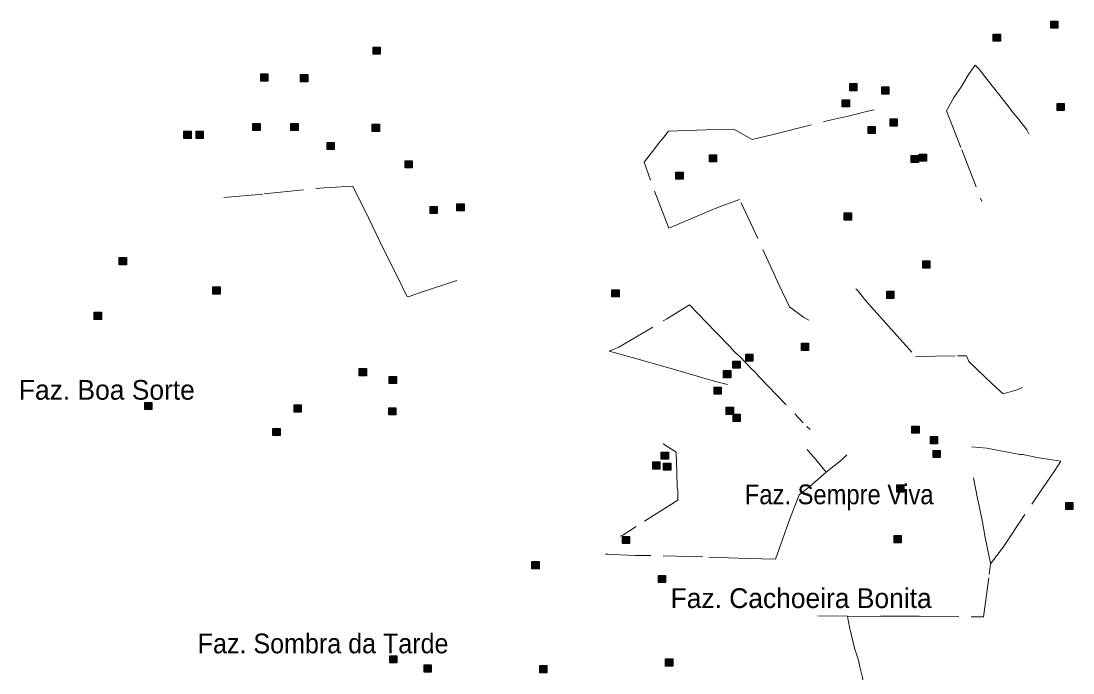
# Model space of a CAD drawing. Extents: x 393.5 to 446.9, y 8064.8 to 8120.4.
# Drawn here: x 417.84 to 426.38, y 8104.16 to 8109.45 of the extents above; entities that cross this region are included whole.
import ezdxf

# ---------------------------------------------------------------- set-up
doc = ezdxf.new("R2010")
doc.units = 0
doc.header["$LTSCALE"] = 0.064
doc.linetypes.add('DOT_DASHED', pattern=[7.7, 5, -1.2, 0.3, -1.2])
doc.layers.add('2', color=7, linetype='Continuous', lineweight=25)
doc.layers.add('22', color=7, linetype='DOT_DASHED', lineweight=13)
doc.layers.add('61', color=7, linetype='Continuous')

msp = doc.modelspace()

# ---------------------------------------------------------------- hatches: boundary and pattern name
at = {"layer": '2'}
for points in [[(426.1945, 8109.4478), (426.2525, 8109.4478), (426.2525, 8109.3898), (426.1945, 8109.3898)], [(425.7282, 8109.3416), (425.7862, 8109.3416), (425.7862, 8109.2836), (425.7282, 8109.2836)], [(420.6996, 8109.2372), (420.7576, 8109.2372), (420.7576, 8109.1792), (420.6996, 8109.1792)], [(419.7879, 8109.0185), (419.8459, 8109.0185), (419.8459, 8108.9605), (419.7879, 8108.9605)], [(420.1104, 8109.013), (420.1684, 8109.013), (420.1684, 8108.955), (420.1104, 8108.955)], [(424.565, 8108.941), (424.623, 8108.941), (424.623, 8108.883), (424.565, 8108.883)], [(424.8245, 8108.9129), (424.8825, 8108.9129), (424.8825, 8108.8549), (424.8245, 8108.8549)], [(424.5039, 8108.8094), (424.5619, 8108.8094), (424.5619, 8108.7514), (424.5039, 8108.7514)], [(426.247, 8108.7795), (426.305, 8108.7795), (426.305, 8108.7215), (426.247, 8108.7215)], [(419.7247, 8108.6181), (419.7827, 8108.6181), (419.7827, 8108.5601), (419.7247, 8108.5601)], [(420.0328, 8108.6181), (420.0908, 8108.6181), (420.0908, 8108.5601), (420.0328, 8108.5601)], [(420.6916, 8108.6109), (420.7496, 8108.6109), (420.7496, 8108.5529), (420.6916, 8108.5529)], [(424.8917, 8108.6537), (424.9497, 8108.6537), (424.9497, 8108.5957), (424.8917, 8108.5957)], [(419.165, 8108.5539), (419.223, 8108.5539), (419.223, 8108.4959), (419.165, 8108.4959)], [(419.2628, 8108.5542), (419.3208, 8108.5542), (419.3208, 8108.4962), (419.2628, 8108.4962)], [(424.7134, 8108.5925), (424.7714, 8108.5925), (424.7714, 8108.5345), (424.7134, 8108.5345)], [(420.3263, 8108.4635), (420.3843, 8108.4635), (420.3843, 8108.4055), (420.3263, 8108.4055)], [(423.4268, 8108.3637), (423.4848, 8108.3637), (423.4848, 8108.3057), (423.4268, 8108.3057)], [(425.0632, 8108.3574), (425.1212, 8108.3574), (425.1212, 8108.2994), (425.0632, 8108.2994)], [(425.1284, 8108.3685), (425.1864, 8108.3685), (425.1864, 8108.3105), (425.1284, 8108.3105)], [(420.9578, 8108.315), (421.0158, 8108.315), (421.0158, 8108.257), (420.9578, 8108.257)], [(423.1546, 8108.2232), (423.2126, 8108.2232), (423.2126, 8108.1652), (423.1546, 8108.1652)], [(421.1617, 8107.9449), (421.2197, 8107.9449), (421.2197, 8107.8869), (421.1617, 8107.8869)], [(421.3791, 8107.9659), (421.4371, 8107.9659), (421.4371, 8107.9079), (421.3791, 8107.9079)], [(424.5206, 8107.8914), (424.5786, 8107.8914), (424.5786, 8107.8334), (424.5206, 8107.8334)], [(418.6404, 8107.5295), (418.6984, 8107.5295), (418.6984, 8107.4715), (418.6404, 8107.4715)], [(425.1572, 8107.5023), (425.2152, 8107.5023), (425.2152, 8107.4443), (425.1572, 8107.4443)], [(419.3999, 8107.2915), (419.4579, 8107.2915), (419.4579, 8107.2335), (419.3999, 8107.2335)], [(422.6356, 8107.2684), (422.6936, 8107.2684), (422.6936, 8107.2104), (422.6356, 8107.2104)], [(424.8646, 8107.2557), (424.9226, 8107.2557), (424.9226, 8107.1977), (424.8646, 8107.1977)], [(418.4378, 8107.086), (418.4958, 8107.086), (418.4958, 8107.028), (418.4378, 8107.028)], [(424.1722, 8106.8348), (424.2302, 8106.8348), (424.2302, 8106.7768), (424.1722, 8106.7768)], [(423.7217, 8106.7463), (423.7797, 8106.7463), (423.7797, 8106.6883), (423.7217, 8106.6883)], [(423.6174, 8106.6897), (423.6754, 8106.6897), (423.6754, 8106.6317), (423.6174, 8106.6317)], [(420.5871, 8106.6285), (420.6451, 8106.6285), (420.6451, 8106.5705), (420.5871, 8106.5705)], [(420.8306, 8106.5661), (420.8886, 8106.5661), (420.8886, 8106.5081), (420.8306, 8106.5081)], [(423.5416, 8106.6132), (423.5996, 8106.6132), (423.5996, 8106.5552), (423.5416, 8106.5552)], [(423.4644, 8106.4793), (423.5224, 8106.4793), (423.5224, 8106.4213), (423.4644, 8106.4213)], [(418.8468, 8106.3551), (418.9048, 8106.3551), (418.9048, 8106.2971), (418.8468, 8106.2971)], [(420.0577, 8106.3341), (420.1157, 8106.3341), (420.1157, 8106.2761), (420.0577, 8106.2761)], [(420.8258, 8106.3116), (420.8838, 8106.3116), (420.8838, 8106.2536), (420.8258, 8106.2536)], [(423.5636, 8106.3153), (423.6216, 8106.3153), (423.6216, 8106.2573), (423.5636, 8106.2573)], [(423.6193, 8106.259), (423.6773, 8106.259), (423.6773, 8106.201), (423.6193, 8106.201)], [(419.8868, 8106.143), (419.9448, 8106.143), (419.9448, 8106.085), (419.8868, 8106.085)], [(425.0694, 8106.1632), (425.1274, 8106.1632), (425.1274, 8106.1052), (425.0694, 8106.1052)], [(425.2191, 8106.0779), (425.2771, 8106.0779), (425.2771, 8106.0199), (425.2191, 8106.0199)], [(423.0366, 8105.9511), (423.0946, 8105.9511), (423.0946, 8105.8931), (423.0366, 8105.8931)], [(425.2402, 8105.9651), (425.2982, 8105.9651), (425.2982, 8105.9071), (425.2402, 8105.9071)], [(422.9666, 8105.8726), (423.0246, 8105.8726), (423.0246, 8105.8146), (422.9666, 8105.8146)], [(423.0544, 8105.863), (423.1124, 8105.863), (423.1124, 8105.805), (423.0544, 8105.805)], [(424.9457, 8105.6853), (425.0037, 8105.6853), (425.0037, 8105.6273), (424.9457, 8105.6273)], [(426.317, 8105.5437), (426.375, 8105.5437), (426.375, 8105.4857), (426.317, 8105.4857)], [(422.7209, 8105.2682), (422.7789, 8105.2682), (422.7789, 8105.2102), (422.7209, 8105.2102)], [(424.9249, 8105.2746), (424.9829, 8105.2746), (424.9829, 8105.2166), (424.9249, 8105.2166)], [(421.9874, 8105.0637), (422.0454, 8105.0637), (422.0454, 8105.0057), (421.9874, 8105.0057)], [(423.0128, 8104.9511), (423.0708, 8104.9511), (423.0708, 8104.8931), (423.0128, 8104.8931)], [(420.834, 8104.2992), (420.892, 8104.2992), (420.892, 8104.2412), (420.834, 8104.2412)], [(423.0714, 8104.2747), (423.1294, 8104.2747), (423.1294, 8104.2167), (423.0714, 8104.2167)], [(421.1124, 8104.2256), (421.1704, 8104.2256), (421.1704, 8104.1676), (421.1124, 8104.1676)], [(422.0501, 8104.2198), (422.1081, 8104.2198), (422.1081, 8104.1618), (422.0501, 8104.1618)]]:
    msp.add_hatch(color=256, dxfattribs=at).paths.add_polyline_path(points)

# ---------------------------------------------------------------- linework, layer by layer
for points in [[(426.1945, 8109.4478), (426.2525, 8109.4478), (426.2525, 8109.3898), (426.1945, 8109.3898)], [(425.7282, 8109.3416), (425.7862, 8109.3416), (425.7862, 8109.2836), (425.7282, 8109.2836)], [(420.6996, 8109.2372), (420.7576, 8109.2372), (420.7576, 8109.1792), (420.6996, 8109.1792)], [(419.7879, 8109.0185), (419.8459, 8109.0185), (419.8459, 8108.9605), (419.7879, 8108.9605)], [(420.1104, 8109.013), (420.1684, 8109.013), (420.1684, 8108.955), (420.1104, 8108.955)], [(424.565, 8108.941), (424.623, 8108.941), (424.623, 8108.883), (424.565, 8108.883)], [(424.8245, 8108.9129), (424.8825, 8108.9129), (424.8825, 8108.8549), (424.8245, 8108.8549)], [(424.5039, 8108.8094), (424.5619, 8108.8094), (424.5619, 8108.7514), (424.5039, 8108.7514)], [(426.247, 8108.7795), (426.305, 8108.7795), (426.305, 8108.7215), (426.247, 8108.7215)], [(419.7247, 8108.6181), (419.7827, 8108.6181), (419.7827, 8108.5601), (419.7247, 8108.5601)], [(420.0328, 8108.6181), (420.0908, 8108.6181), (420.0908, 8108.5601), (420.0328, 8108.5601)], [(420.6916, 8108.6109), (420.7496, 8108.6109), (420.7496, 8108.5529), (420.6916, 8108.5529)], [(424.8917, 8108.6537), (424.9497, 8108.6537), (424.9497, 8108.5957), (424.8917, 8108.5957)], [(419.165, 8108.5539), (419.223, 8108.5539), (419.223, 8108.4959), (419.165, 8108.4959)], [(419.2628, 8108.5542), (419.3208, 8108.5542), (419.3208, 8108.4962), (419.2628, 8108.4962)], [(424.7134, 8108.5925), (424.7714, 8108.5925), (424.7714, 8108.5345), (424.7134, 8108.5345)], [(420.3263, 8108.4635), (420.3843, 8108.4635), (420.3843, 8108.4055), (420.3263, 8108.4055)], [(423.4268, 8108.3637), (423.4848, 8108.3637), (423.4848, 8108.3057), (423.4268, 8108.3057)], [(425.0632, 8108.3574), (425.1212, 8108.3574), (425.1212, 8108.2994), (425.0632, 8108.2994)], [(425.1284, 8108.3685), (425.1864, 8108.3685), (425.1864, 8108.3105), (425.1284, 8108.3105)], [(420.9578, 8108.315), (421.0158, 8108.315), (421.0158, 8108.257), (420.9578, 8108.257)], [(423.1546, 8108.2232), (423.2126, 8108.2232), (423.2126, 8108.1652), (423.1546, 8108.1652)], [(421.1617, 8107.9449), (421.2197, 8107.9449), (421.2197, 8107.8869), (421.1617, 8107.8869)], [(421.3791, 8107.9659), (421.4371, 8107.9659), (421.4371, 8107.9079), (421.3791, 8107.9079)], [(424.5206, 8107.8914), (424.5786, 8107.8914), (424.5786, 8107.8334), (424.5206, 8107.8334)], [(418.6404, 8107.5295), (418.6984, 8107.5295), (418.6984, 8107.4715), (418.6404, 8107.4715)], [(425.1572, 8107.5023), (425.2152, 8107.5023), (425.2152, 8107.4443), (425.1572, 8107.4443)], [(419.3999, 8107.2915), (419.4579, 8107.2915), (419.4579, 8107.2335), (419.3999, 8107.2335)], [(422.6356, 8107.2684), (422.6936, 8107.2684), (422.6936, 8107.2104), (422.6356, 8107.2104)], [(424.8646, 8107.2557), (424.9226, 8107.2557), (424.9226, 8107.1977), (424.8646, 8107.1977)], [(418.4378, 8107.086), (418.4958, 8107.086), (418.4958, 8107.028), (418.4378, 8107.028)], [(424.1722, 8106.8348), (424.2302, 8106.8348), (424.2302, 8106.7768), (424.1722, 8106.7768)], [(423.7217, 8106.7463), (423.7797, 8106.7463), (423.7797, 8106.6883), (423.7217, 8106.6883)], [(423.6174, 8106.6897), (423.6754, 8106.6897), (423.6754, 8106.6317), (423.6174, 8106.6317)], [(420.5871, 8106.6285), (420.6451, 8106.6285), (420.6451, 8106.5705), (420.5871, 8106.5705)], [(420.8306, 8106.5661), (420.8886, 8106.5661), (420.8886, 8106.5081), (420.8306, 8106.5081)], [(423.5416, 8106.6132), (423.5996, 8106.6132), (423.5996, 8106.5552), (423.5416, 8106.5552)], [(423.4644, 8106.4793), (423.5224, 8106.4793), (423.5224, 8106.4213), (423.4644, 8106.4213)], [(418.8468, 8106.3551), (418.9048, 8106.3551), (418.9048, 8106.2971), (418.8468, 8106.2971)], [(420.0577, 8106.3341), (420.1157, 8106.3341), (420.1157, 8106.2761), (420.0577, 8106.2761)], [(420.8258, 8106.3116), (420.8838, 8106.3116), (420.8838, 8106.2536), (420.8258, 8106.2536)], [(423.5636, 8106.3153), (423.6216, 8106.3153), (423.6216, 8106.2573), (423.5636, 8106.2573)], [(423.6193, 8106.259), (423.6773, 8106.259), (423.6773, 8106.201), (423.6193, 8106.201)], [(419.8868, 8106.143), (419.9448, 8106.143), (419.9448, 8106.085), (419.8868, 8106.085)], [(425.0694, 8106.1632), (425.1274, 8106.1632), (425.1274, 8106.1052), (425.0694, 8106.1052)], [(425.2191, 8106.0779), (425.2771, 8106.0779), (425.2771, 8106.0199), (425.2191, 8106.0199)], [(423.0366, 8105.9511), (423.0946, 8105.9511), (423.0946, 8105.8931), (423.0366, 8105.8931)], [(425.2402, 8105.9651), (425.2982, 8105.9651), (425.2982, 8105.9071), (425.2402, 8105.9071)], [(422.9666, 8105.8726), (423.0246, 8105.8726), (423.0246, 8105.8146), (422.9666, 8105.8146)], [(423.0544, 8105.863), (423.1124, 8105.863), (423.1124, 8105.805), (423.0544, 8105.805)], [(424.9457, 8105.6853), (425.0037, 8105.6853), (425.0037, 8105.6273), (424.9457, 8105.6273)], [(426.317, 8105.5437), (426.375, 8105.5437), (426.375, 8105.4857), (426.317, 8105.4857)], [(422.7209, 8105.2682), (422.7789, 8105.2682), (422.7789, 8105.2102), (422.7209, 8105.2102)], [(424.9249, 8105.2746), (424.9829, 8105.2746), (424.9829, 8105.2166), (424.9249, 8105.2166)], [(421.9874, 8105.0637), (422.0454, 8105.0637), (422.0454, 8105.0057), (421.9874, 8105.0057)], [(423.0128, 8104.9511), (423.0708, 8104.9511), (423.0708, 8104.8931), (423.0128, 8104.8931)], [(420.834, 8104.2992), (420.892, 8104.2992), (420.892, 8104.2412), (420.834, 8104.2412)], [(423.0714, 8104.2747), (423.1294, 8104.2747), (423.1294, 8104.2167), (423.0714, 8104.2167)], [(421.1124, 8104.2256), (421.1704, 8104.2256), (421.1704, 8104.1676), (421.1124, 8104.1676)], [(422.0501, 8104.2198), (422.1081, 8104.2198), (422.1081, 8104.1618), (422.0501, 8104.1618)]]:
    msp.add_lwpolyline(points, close=True, dxfattribs=at)
at = {"layer": '22'}
for p, q in [((424.6149, 8107.2751), (424.6237, 8107.2678)), ((424.3737, 8105.7897), (424.2435, 8105.6756))]:
    msp.add_line(p, q, dxfattribs=at)
for points in [[(425.8668, 8108.7352), (425.8595, 8108.7449), (425.781, 8108.8442), (425.6801, 8108.9738), (425.6144, 8109.0586), (425.5808, 8109.089), (425.5344, 8109.0218), (425.4655, 8108.9082), (425.4094, 8108.8281), (425.3486, 8108.7193), (425.4745, 8108.4027), (425.6355, 8107.9856)], [(423.0054, 8108.4446), (423.0677, 8108.5202), (423.0903, 8108.5488), (423.0985, 8108.5551), (423.3998, 8108.5652), (423.6248, 8108.57), (423.774, 8108.4872), (423.9435, 8108.5276), (424.3919, 8108.6399), (424.5632, 8108.6786), (424.6995, 8108.7136), (424.7621, 8108.7283)], [(426.0183, 8108.5328), (426.002, 8108.566), (425.9283, 8108.6588), (425.8883, 8108.7069), (425.8668, 8108.7352)], [(423.3699, 8107.8842), (423.333, 8107.8683), (423.1681, 8107.7978), (423.0973, 8107.7683), (422.9481, 8108.1566), (422.8983, 8108.3038), (422.9831, 8108.4143), (423.0054, 8108.4446)], [(419.4871, 8108.0153), (419.8164, 8108.0455), (420.3006, 8108.0953), (420.5354, 8108.1078), (420.6628, 8107.853), (420.7888, 8107.5855), (420.9046, 8107.3578), (420.9729, 8107.2174), (420.9843, 8107.2098), (421.0755, 8107.2421), (421.4476, 8107.3673)], [(424.2339, 8107.0222), (424.1928, 8107.043), (424.0755, 8107.1303), (423.9931, 8107.3049), (423.8184, 8107.684), (423.6711, 8108.0008), (423.5014, 8107.9384), (423.4215, 8107.906), (423.3699, 8107.8842)], [(424.6237, 8107.2678), (424.6955, 8107.179), (424.8553, 8106.9995), (425.0985, 8106.7281), (425.4386, 8106.7324), (425.5107, 8106.7324), (425.5305, 8106.6872), (425.7228, 8106.5021), (425.8077, 8106.4244), (425.9215, 8106.4569), (425.9668, 8106.4752)], [(423.572, 8106.5013), (423.4765, 8106.5254), (423.373, 8106.5541), (423.1048, 8106.6326), (422.8002, 8106.7188), (422.6124, 8106.7704), (422.691, 8106.803), (423.0799, 8107.0327), (423.2657, 8107.1457), (423.4784, 8106.9255), (423.5895, 8106.8106), (423.6317, 8106.7628), (423.6758, 8106.7238), (423.7614, 8106.6331), (423.7997, 8106.5986)], [(423.7997, 8106.5986), (423.8285, 8106.5661), (424.2164, 8106.1593), (424.2439, 8106.1358)], [(423.0526, 8106.0197), (423.1568, 8105.9523), (423.1628, 8105.7943), (423.1659, 8105.6607)], [(424.3737, 8105.7897), (424.2752, 8105.9085), (424.245, 8105.9433), (424.2192, 8105.9719)], [(425.5528, 8105.9937), (425.6754, 8105.9823), (425.831, 8105.9526), (425.9448, 8105.9329), (425.9745, 8105.9314)], [(424.3737, 8105.7897), (424.5033, 8105.8916), (424.5416, 8105.9284)], [(425.7072, 8105.0466), (425.8078, 8105.1797), (426.0729, 8105.5785), (426.2226, 8105.793), (426.2779, 8105.8791), (426.1704, 8105.8933), (426.0827, 8105.9074), (425.995, 8105.9272), (425.9786, 8105.9306), (425.9745, 8105.9314)], [(425.5675, 8105.7417), (425.6012, 8105.5756), (425.6386, 8105.3999), (425.6635, 8105.2596), (425.7064, 8105.0503), (425.7072, 8105.0466)], [(423.1659, 8105.6607), (423.1693, 8105.6425), (423.1693, 8105.5628), (422.8321, 8105.3494), (422.7242, 8105.2793), (422.7017, 8105.2691)], [(424.2435, 8105.6756), (424.1546, 8105.6038), (424.0704, 8105.3889), (424.019, 8105.2434), (423.9623, 8105.0845), (423.7419, 8105.0899), (423.3725, 8105.102), (422.9324, 8105.114)], [(422.9324, 8105.114), (422.8242, 8105.1127), (422.706, 8105.1181), (422.6031, 8105.1234), (422.5831, 8105.1248)], [(424.6252, 8104.6189), (424.812, 8104.6212), (425.1292, 8104.6212), (425.6486, 8104.6145), (425.6961, 8104.9596), (425.7072, 8105.0466)], [(424.3049, 8104.6234), (424.547, 8104.6213), (424.5472, 8104.6213), (424.6252, 8104.6189)], [(424.6782, 8104.0665), (424.6679, 8104.1234), (424.6478, 8104.2105), (424.6344, 8104.2641), (424.6031, 8104.3623), (424.5629, 8104.5319), (424.5476, 8104.619), (424.5472, 8104.6213)]]:
    msp.add_lwpolyline(points, dxfattribs=at)

# ---------------------------------------------------------------- texts
at = {"layer": '61'}
for s, p in [('Faz. Boa Sorte', (417.8262, 8106.3766)), ('Faz. Cachoeira Bonita', (423.1119, 8104.6872))]:
    msp.add_text(s, height=0.16, dxfattribs=at).set_placement(p)
for s, width, p in [('Faz. Sempre Viva', 0.9, (423.7138, 8105.5287)), ('Faz. Sombra da Tarde', 0.95, (419.2767, 8104.3199))]:
    msp.add_text(s, height=0.16, dxfattribs=dict(at, width=width)).set_placement(p)

doc.saveas('drawing.dxf')
